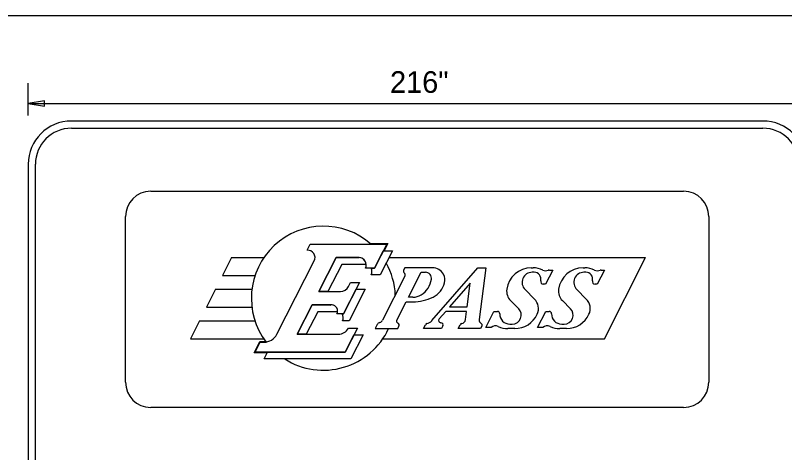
# Model space of a CAD drawing. Extents: x 10268312 to 10268472, y 2142583 to 2142688.
# Drawn here: x 10268433.03 to 10268458.14, y 2142673.26 to 2142687.53 of the extents above; entities that cross this region are included whole.
import ezdxf

# ---------------------------------------------------------------- set-up
doc = ezdxf.new("R2010")
doc.units = 0
for name, color, linetype in [('GSBWFill', 7, 'Continuous'), ('GSDims', 7, 'Continuous'), ('SignPanel', 7, 'Continuous'), ('SumBoxLines_dp', 7, 'Continuous')]:
    doc.layers.add(name, color=color, linetype=linetype)

msp = doc.modelspace()

# ---------------------------------------------------------------- linework, layer by layer
at = {"layer": 'GSBWFill'}
for p, q in [((10268433.445, 2142684.26), (10268433.445, 2142685.318)), ((10268457.434, 2142684.084), (10268434.856, 2142684.084)), ((10268434.856, 2142683.849), (10268457.434, 2142683.849))]:
    msp.add_line(p, q, dxfattribs=at)
msp.add_lwpolyline([(10268433.445, 2142682.673), (10268433.445, 2142666.857), (10268433.68, 2142666.857), (10268433.68, 2142682.673)], dxfattribs=at)
for centre, radius, start, end in [((10268434.856, 2142682.673), 1.411, 90, 180), ((10268457.434, 2142682.673), 1.411, 0, 90), ((10268434.856, 2142682.673), 1.176, 90, 180), ((10268457.434, 2142682.673), 1.176, 0, 90)]:
    msp.add_arc(centre, radius, start, end, dxfattribs=at)
at = {"layer": 'GSDims'}
msp.add_line((10268433.445, 2142684.657), (10268458.846, 2142684.657), dxfattribs=at)
msp.add_lwpolyline([(10268433.445, 2142684.657), (10268433.974, 2142684.569), (10268433.974, 2142684.745)], close=True, dxfattribs=at)
at = {"layer": 'SignPanel'}
for p, q in [((10268437.445, 2142681.791), (10268454.845, 2142681.791)), ((10268436.622, 2142675.56), (10268436.622, 2142680.968)), ((10268455.668, 2142680.968), (10268455.668, 2142675.56)), ((10268442.551, 2142679.869), (10268442.651, 2142680.066)), ((10268442.651, 2142680.066), (10268445.15, 2142680.066)), ((10268444.612, 2142680.088), (10268445.185, 2142680.088)), ((10268445.15, 2142680.066), (10268444.749, 2142679.281)), ((10268445.185, 2142680.088), (10268445.062, 2142679.846)), ((10268440.085, 2142679.625), (10268439.785, 2142679.038)), ((10268440.085, 2142679.625), (10268441.138, 2142679.625)), ((10268443.498, 2142679.625), (10268442.936, 2142678.523)), ((10268442.936, 2142678.523), (10268443.498, 2142679.625)), ((10268444.247, 2142679.625), (10268443.498, 2142679.625)), ((10268443.498, 2142679.625), (10268444.247, 2142679.625)), ((10268444.749, 2142679.28), (10268445.037, 2142679.846)), ((10268445.334, 2142679.846), (10268444.934, 2142679.06)), ((10268445.037, 2142679.846), (10268445.334, 2142679.846)), ((10268445.221, 2142679.625), (10268453.605, 2142679.625)), ((10268452.257, 2142676.98), (10268453.605, 2142679.625)), ((10268441.563, 2142677.123), (10268442.783, 2142679.517)), ((10268443.682, 2142679.405), (10268443.233, 2142678.523)), ((10268444.482, 2142679.405), (10268443.682, 2142679.405)), ((10268444.749, 2142679.281), (10268444.455, 2142679.281)), ((10268444.639, 2142679.28), (10268444.749, 2142679.28)), ((10268445.743, 2142679.295), (10268445.702, 2142679.216)), ((10268446.642, 2142679.295), (10268445.743, 2142679.295)), ((10268445.858, 2142678.332), (10268446.274, 2142679.148)), ((10268445.858, 2142678.332), (10268446.274, 2142679.148)), ((10268446.274, 2142679.148), (10268446.415, 2142679.148)), ((10268446.274, 2142679.148), (10268446.415, 2142679.148)), ((10268446.62, 2142677.569), (10268448.121, 2142679.295)), ((10268448.121, 2142679.295), (10268448.385, 2142679.295)), ((10268448.385, 2142679.295), (10268448.165, 2142677.604)), ((10268449.871, 2142679.295), (10268449.927, 2142679.295)), ((10268449.965, 2142679.148), (10268449.902, 2142679.148)), ((10268450.571, 2142679.221), (10268450.337, 2142678.763)), ((10268450.461, 2142679.221), (10268450.571, 2142679.221)), ((10268451.562, 2142679.295), (10268451.617, 2142679.295)), ((10268451.655, 2142679.148), (10268451.592, 2142679.148)), ((10268452.261, 2142679.221), (10268452.027, 2142678.763)), ((10268452.15, 2142679.221), (10268452.261, 2142679.221)), ((10268439.785, 2142679.038), (10268440.849, 2142679.038)), ((10268444.934, 2142679.06), (10268444.64, 2142679.06)), ((10268445.745, 2142679.017), (10268445.017, 2142677.589)), ((10268444.263, 2142678.817), (10268443.739, 2142677.788)), ((10268443.901, 2142678.684), (10268443.969, 2142678.817)), ((10268443.969, 2142678.817), (10268444.263, 2142678.817)), ((10268447.874, 2142678.788), (10268447.204, 2142678.016)), ((10268447.874, 2142678.788), (10268447.204, 2142678.016)), ((10268447.774, 2142678.016), (10268447.874, 2142678.788)), ((10268447.774, 2142678.016), (10268447.874, 2142678.788)), ((10268450.337, 2142678.763), (10268450.264, 2142678.763)), ((10268452.027, 2142678.763), (10268451.954, 2142678.763)), ((10268439.561, 2142678.597), (10268439.262, 2142678.009)), ((10268439.561, 2142678.597), (10268440.749, 2142678.597)), ((10268442.936, 2142678.523), (10268443.639, 2142678.523)), ((10268443.233, 2142678.523), (10268442.936, 2142678.523)), ((10268443.739, 2142677.788), (10268444.151, 2142678.597)), ((10268444.448, 2142678.597), (10268443.923, 2142677.568)), ((10268444.151, 2142678.597), (10268444.448, 2142678.597)), ((10268449.668, 2142678.583), (10268449.976, 2142678.275)), ((10268451.358, 2142678.583), (10268451.666, 2142678.275)), ((10268445.479, 2142677.589), (10268445.783, 2142678.185)), ((10268445.783, 2142678.185), (10268446.003, 2142678.185)), ((10268446.003, 2142678.332), (10268445.858, 2142678.332)), ((10268446.003, 2142678.332), (10268445.858, 2142678.332)), ((10268449.46, 2142677.96), (10268449.196, 2142678.224)), ((10268451.15, 2142677.96), (10268450.886, 2142678.224)), ((10268439.262, 2142678.009), (10268440.749, 2142678.009)), ((10268442.712, 2142678.082), (10268442.225, 2142677.127)), ((10268442.225, 2142677.127), (10268442.712, 2142678.082)), ((10268442.896, 2142677.861), (10268442.522, 2142677.127)), ((10268443.357, 2142678.082), (10268442.712, 2142678.082)), ((10268442.712, 2142678.082), (10268443.329, 2142678.08)), ((10268443.545, 2142677.859), (10268442.896, 2142677.861)), ((10268447.076, 2142677.869), (10268446.863, 2142677.625)), ((10268447.759, 2142677.869), (10268447.076, 2142677.869)), ((10268447.204, 2142678.016), (10268447.774, 2142678.016)), ((10268447.204, 2142678.016), (10268447.774, 2142678.016)), ((10268447.724, 2142677.604), (10268447.759, 2142677.869)), ((10268448.384, 2142677.348), (10268448.651, 2142677.871)), ((10268448.651, 2142677.871), (10268448.769, 2142677.871)), ((10268450.074, 2142677.348), (10268450.341, 2142677.871)), ((10268450.341, 2142677.871), (10268450.459, 2142677.871)), ((10268443.739, 2142677.788), (10268443.518, 2142677.788)), ((10268443.693, 2142677.788), (10268443.739, 2142677.788)), ((10268439.037, 2142677.568), (10268438.738, 2142676.98)), ((10268439.037, 2142677.568), (10268440.849, 2142677.568)), ((10268443.923, 2142677.568), (10268443.703, 2142677.568)), ((10268444.839, 2142677.44), (10268444.773, 2142677.311)), ((10268445.508, 2142677.311), (10268445.547, 2142677.389)), ((10268446.349, 2142677.311), (10268446.414, 2142677.437)), ((10268446.981, 2142677.396), (10268446.937, 2142677.311)), ((10268447.484, 2142677.311), (10268447.549, 2142677.438)), ((10268448.257, 2142677.387), (10268448.218, 2142677.311)), ((10268448.563, 2142677.348), (10268448.384, 2142677.348)), ((10268449.173, 2142677.458), (10268449.252, 2142677.458)), ((10268450.253, 2142677.348), (10268450.074, 2142677.348)), ((10268450.863, 2142677.458), (10268450.942, 2142677.458)), ((10268442.225, 2142677.127), (10268443.574, 2142677.127)), ((10268442.522, 2142677.127), (10268442.225, 2142677.127)), ((10268444.194, 2142677.325), (10268443.793, 2142676.539)), ((10268443.793, 2142676.539), (10268444.081, 2142677.105)), ((10268443.899, 2142677.325), (10268444.194, 2142677.325)), ((10268444.378, 2142677.105), (10268443.978, 2142676.319)), ((10268444.081, 2142677.105), (10268444.378, 2142677.105)), ((10268444.773, 2142677.311), (10268445.508, 2142677.311)), ((10268446.937, 2142677.311), (10268446.349, 2142677.311)), ((10268448.218, 2142677.311), (10268447.484, 2142677.311)), ((10268449.331, 2142677.311), (10268449.11, 2142677.311)), ((10268451.021, 2142677.311), (10268450.8, 2142677.311)), ((10268438.738, 2142676.98), (10268441.138, 2142676.98)), ((10268440.823, 2142676.52), (10268441.009, 2142676.886)), ((10268440.854, 2142676.539), (10268441.021, 2142676.867)), ((10268441.009, 2142676.886), (10268441.144, 2142676.886)), ((10268441.021, 2142676.867), (10268441.144, 2142676.867)), ((10268445.027, 2142676.98), (10268452.257, 2142676.98)), ((10268441.25, 2142676.52), (10268440.823, 2142676.52)), ((10268443.793, 2142676.539), (10268440.854, 2142676.539)), ((10268441.148, 2142676.319), (10268441.26, 2142676.539)), ((10268441.26, 2142676.539), (10268443.793, 2142676.539)), ((10268443.978, 2142676.319), (10268441.148, 2142676.319)), ((10268454.845, 2142674.737), (10268437.445, 2142674.737))]:
    msp.add_line(p, q, dxfattribs=at)
for centre, radius, start, end in [((10268437.445, 2142680.968), 0.823, 90, 180), ((10268454.845, 2142680.968), 0.823, 0, 90), ((10268443.082, 2142678.303), 2.351, 48.5904, 217.4727), ((10268442.567, 2142679.627), 0.242, 332.9998, 93.8045), ((10268444.247, 2142679.39), 0.235, 332.2089, 90), ((10268444.247, 2142679.39), 0.235, 3.5833, 90), ((10268443.082, 2142678.303), 2.351, 2.4236, 29.2771), ((10268444.431, 2142679.17), 0.235, 332.2089, 27.9127), ((10268445.768, 2142679.183), 0.0735, 152.9784, 231.1602), ((10268445.666, 2142679.057), 0.0882, 333.0027, 51.1602), ((10268446.415, 2142678.949), 0.198, 351.076, 90), ((10268446.415, 2142678.949), 0.198, 351.076, 90), ((10268446.642, 2142678.876), 0.419, 29.4315, 90), ((10268449.871, 2142678.486), 0.808, 90, 172.3089), ((10268449.902, 2142678.817), 0.331, 90, 225), ((10268449.927, 2142678.56), 0.735, 64.0896, 90), ((10268449.965, 2142678.927), 0.22, 345.6915, 90), ((10268450.345, 2142679.419), 0.22, 244.0896, 292.0347), ((10268450.46, 2142679.133), 0.0882, 90, 112.0347), ((10268451.562, 2142678.486), 0.808, 90, 172.3089), ((10268451.592, 2142678.817), 0.331, 90, 225), ((10268451.617, 2142678.56), 0.735, 64.0896, 90), ((10268451.655, 2142678.927), 0.22, 345.6915, 90), ((10268452.035, 2142679.419), 0.22, 244.0896, 292.0347), ((10268452.15, 2142679.133), 0.0882, 90, 112.0347), ((10268445.885, 2142679.033), 0.735, 302.4206, 351.076), ((10268445.885, 2142679.033), 0.735, 302.4206, 351.076), ((10268446.687, 2142678.901), 0.367, 344.7074, 29.4315), ((10268450.264, 2142678.851), 0.0882, 165.6915, 270), ((10268451.954, 2142678.851), 0.0882, 165.6915, 270), ((10268443.639, 2142678.817), 0.294, 270, 332.9883), ((10268446.333, 2142678.998), 0.735, 296.6431, 344.7074), ((10268446.003, 2142678.846), 0.514, 270, 302.4206), ((10268446.003, 2142678.846), 0.514, 270, 302.4206), ((10268449.507, 2142678.536), 0.441, 172.3089, 225), ((10268451.197, 2142678.536), 0.441, 172.3089, 225), ((10268446.003, 2142679.655), 1.47, 270, 296.6431), ((10268449.664, 2142677.963), 0.441, 334.95, 45), ((10268451.354, 2142677.963), 0.441, 334.95, 45), ((10268443.356, 2142677.891), 0.191, 350.3502, 98.3344), ((10268443.356, 2142677.891), 0.191, 327.421, 90), ((10268448.769, 2142677.798), 0.0735, 358.6664, 90), ((10268449.252, 2142677.752), 0.294, 270, 45), ((10268450.459, 2142677.798), 0.0735, 358.6664, 90), ((10268450.942, 2142677.752), 0.294, 270, 45), ((10268443.542, 2142677.671), 0.191, 327.421, 37.9799), ((10268446.919, 2142677.576), 0.0735, 138.9824, 268.6869), ((10268447.579, 2142677.622), 0.147, 279.2397, 352.5632), ((10268448.282, 2142677.588), 0.118, 172.5884, 241.8673), ((10268449.173, 2142677.788), 0.331, 178.6665, 270), ((10268449.331, 2142678.119), 0.808, 270, 334.95), ((10268450.863, 2142677.788), 0.331, 178.6665, 270), ((10268451.021, 2142678.119), 0.808, 270, 334.95), ((10268444.97, 2142677.374), 0.147, 106.4317, 152.9742), ((10268444.886, 2142677.655), 0.147, 286.4317, 332.9959), ((10268445.544, 2142677.556), 0.0735, 152.9884, 244.7832), ((10268445.482, 2142677.423), 0.0735, 333.0239, 64.7832), ((10268446.479, 2142677.403), 0.0735, 102.7162, 153.0239), ((10268446.398, 2142677.761), 0.294, 282.7162, 318.9966), ((10268446.915, 2142677.429), 0.0735, 332.9784, 88.6869), ((10268447.614, 2142677.405), 0.0735, 99.2397, 153.0239), ((10268448.192, 2142677.42), 0.0735, 332.9784, 61.8673), ((10268448.703, 2142677.197), 0.206, 64.3795, 133.1892), ((10268449.11, 2142678.045), 0.735, 244.3795, 270), ((10268450.393, 2142677.197), 0.206, 64.3795, 133.1892), ((10268450.8, 2142678.045), 0.735, 244.3795, 270), ((10268441.144, 2142677.337), 0.47, 270, 332.9991), ((10268443.082, 2142678.303), 2.351, 237.5383, 335.047), ((10268443.573, 2142677.494), 0.367, 270, 332.5096), ((10268441.144, 2142677.337), 0.451, 270, 277.5038), ((10268437.445, 2142675.56), 0.823, 180, 270), ((10268454.845, 2142675.56), 0.823, 270, 360)]:
    msp.add_arc(centre, radius, start, end, dxfattribs=at)
at = {"layer": 'SumBoxLines_dp'}
msp.add_line((10268418.73, 2142687.532), (10268470.98, 2142687.532), dxfattribs=at)

# ---------------------------------------------------------------- texts
at = {"layer": 'GSDims'}
msp.add_text('216"', height=0.7056, dxfattribs=at).set_placement((10268445.259, 2142685.004))

doc.saveas('drawing.dxf')
